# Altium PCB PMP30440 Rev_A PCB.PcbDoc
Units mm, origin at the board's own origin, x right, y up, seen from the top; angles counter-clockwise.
Board outline 51.56 x 18.03 mm, 2 copper layers (Top Layer, Bottom Layer), stack 1.575 mm thick; 21 components, 15 nets, 54 pads, 22 vias.
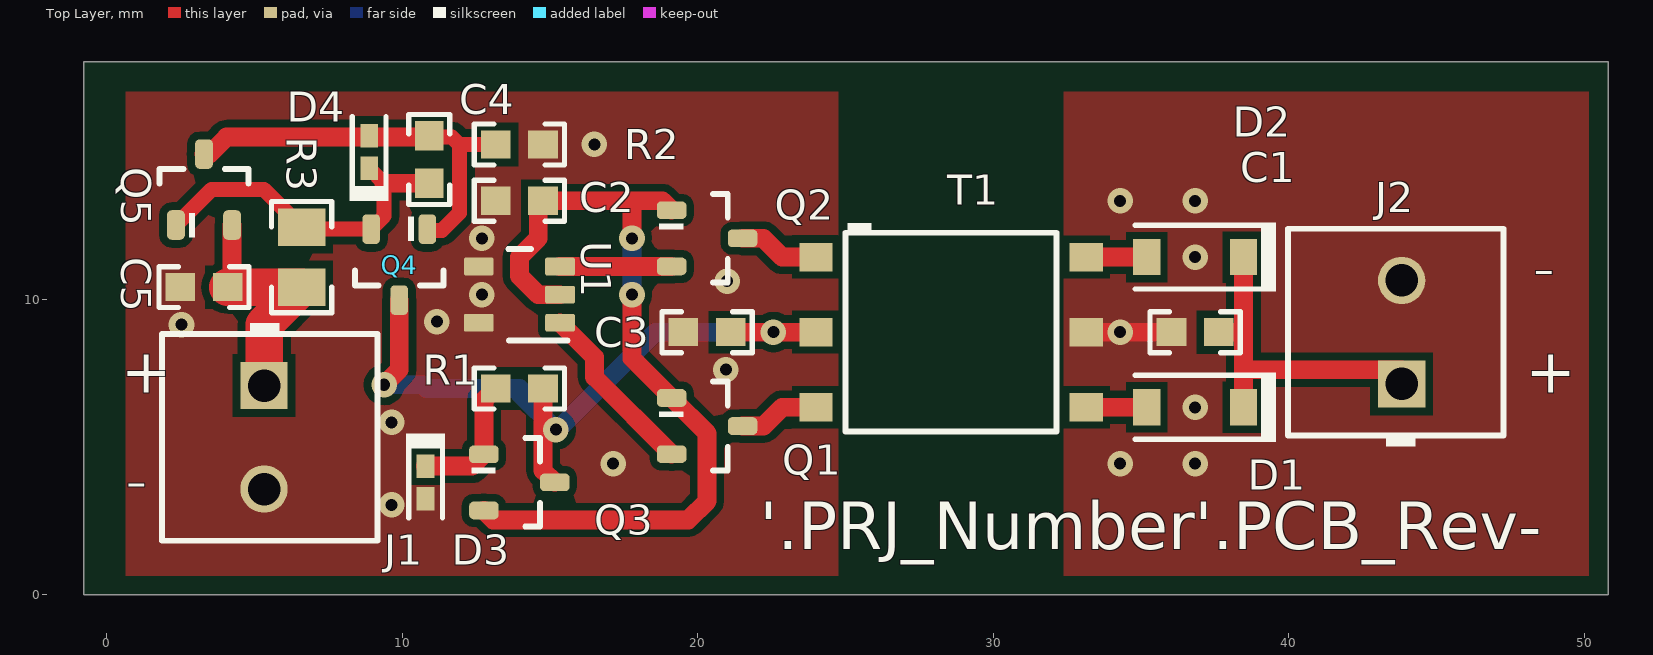
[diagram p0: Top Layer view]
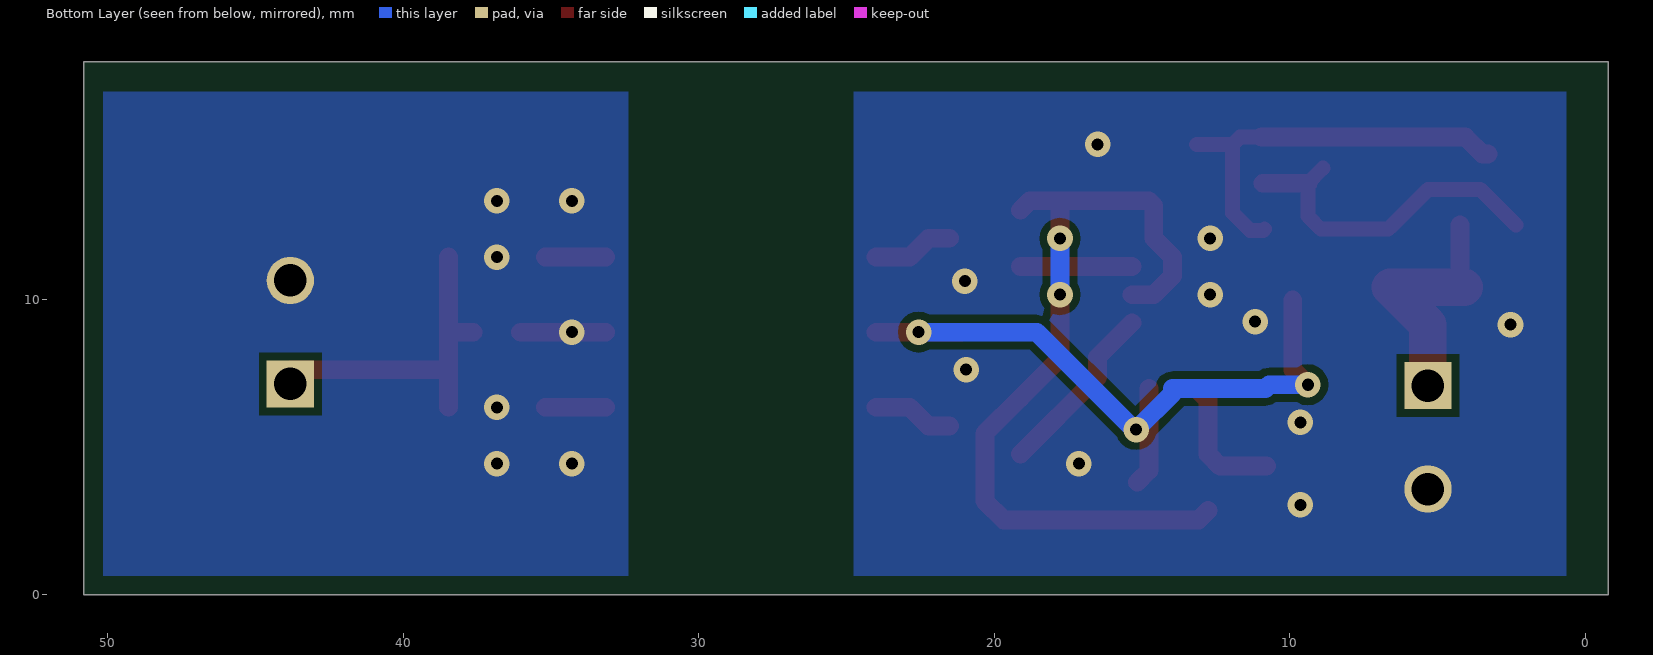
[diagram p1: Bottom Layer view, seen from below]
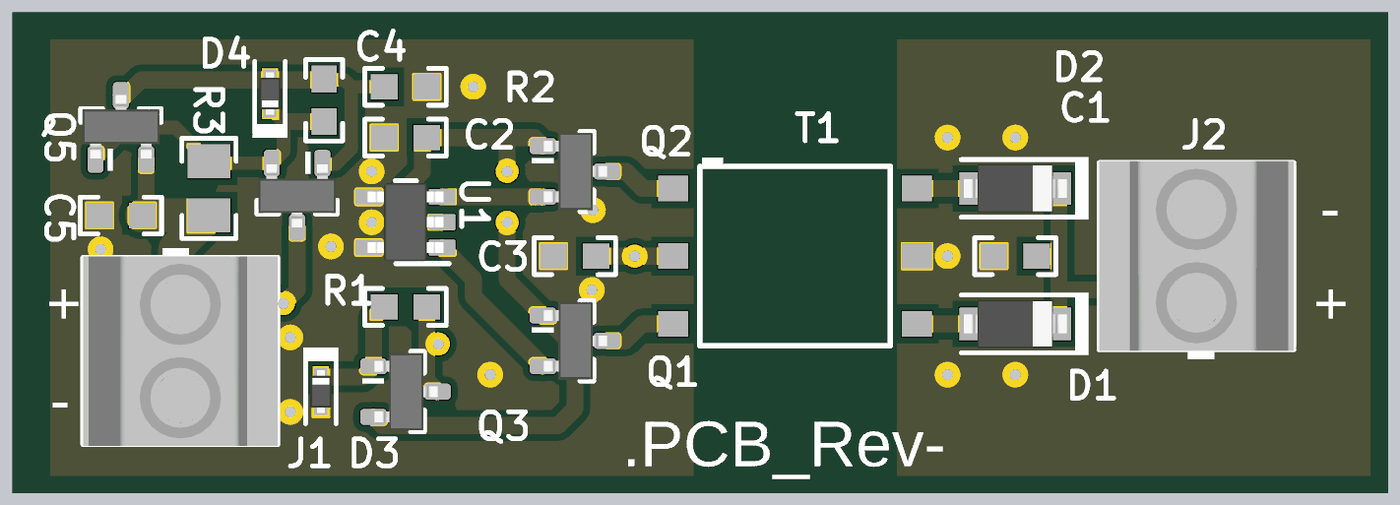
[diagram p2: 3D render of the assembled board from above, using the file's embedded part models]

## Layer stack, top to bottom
Top Solder: solder mask 0.0102, Solder Resist, Dk 3.5
Top Layer: signal copper 0.0356
Dielectric1: core 1.5037, FR-4, Dk 4.8
Bottom Layer: signal copper 0.0356
Bottom Solder: solder mask 0.0102, Solder Resist, Dk 3.5

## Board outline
-0.762,0 50.8,0 50.8,18.034 -0.762,18.034

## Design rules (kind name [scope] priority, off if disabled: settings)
AcuteAngle [All] p1: minimum=4.50000000000000E+0001 checktracksonly=FALSE
AssemblyTestPointUsage [All] p1: valid=2
BoardOutlineClearance BoardOutlineClearance_MountingHoles [OnCopper and InComponentClass('Mounting Holes')] p1: gap=1.016 ignorepadtopadclearanceinfootprint=FALSE
BoardOutlineClearance BoardOutlineClearance_Poly [OnCopper and IsPoly] p2: gap=0.635 ignorepadtopadclearanceinfootprint=FALSE
BoardOutlineClearance [OnCopper and Not InComponentClass('Logo') and not InComponentClass('FiducialMark') and not InRegion(1000,500,4000,800) and not InPoly] p3: gap=1.905 ignorepadtopadclearanceinfootprint=FALSE
Clearance Clearance_4 [InNamedPolygon('TOP_LAYER_GND-S_P006')] p1: gap=0.254 ignorepadtopadclearanceinfootprint=FALSE except(0: Arc-Hole Track-Hole SMDPad-Hole THPad-Hole Via-Hole Fill-Hole Poly-Hole Region-Hole Text-Hole)
Clearance Clearance_3 [InNamedPolygon('BOTTOM_LAYER_GND-S_P004')] p2: gap=0.254 ignorepadtopadclearanceinfootprint=FALSE except(0: Arc-Hole Track-Hole SMDPad-Hole THPad-Hole Via-Hole Fill-Hole Poly-Hole Region-Hole Text-Hole)
Clearance Clearance_2 [InNamedPolygon('BOTTOM_LAYER_GND-P_P002')] p3: gap=0.254 ignorepadtopadclearanceinfootprint=FALSE except(0: Arc-Hole Track-Hole SMDPad-Hole THPad-Hole Via-Hole Fill-Hole Poly-Hole Region-Hole Text-Hole)
Clearance Clearance_1 [InNamedPolygon('TOP_LAYER_GND-P_P000')] p4: gap=0.254 ignorepadtopadclearanceinfootprint=FALSE except(0: Arc-Hole Track-Hole SMDPad-Hole THPad-Hole Via-Hole Fill-Hole Poly-Hole Region-Hole Text-Hole)
Clearance Clearance_Keepouts [((IsTrack Or IsArc) And Not InPoly) And IsFree and IsKeepOut vs ((IsTrack Or IsArc) And Not InPoly) And IsFree and IsKeepOut] p5: gap=0 ignorepadtopadclearanceinfootprint=FALSE
Clearance Clearance_Poly [InPolygon] p6: gap=0.635 ignorepadtopadclearanceinfootprint=FALSE except(0: Arc-Hole Track-Hole SMDPad-Hole THPad-Hole Via-Hole Fill-Hole Poly-Hole Region-Hole Text-Hole)
Clearance Clearance_FiducialMark [IsKeepOut and InComponentClass('FiducialMark') vs IsPad and InComponentClass('FiducialMark')] p7: gap=0 ignorepadtopadclearanceinfootprint=FALSE
Clearance [All] p8: gap=0.2 ignorepadtopadclearanceinfootprint=FALSE except(0: Arc-Hole Track-Hole SMDPad-Hole THPad-Hole Via-Hole Fill-Hole Poly-Hole Region-Hole Text-Hole)
ComponentClearance ComponentClearance_MountingHoles_FiducialMarks [InComponentClass('Mounting Holes') vs InComponentClass('FiducialMark')] p1: gap=1.27 collisioncheckmode=3 verticalgap=0.254 showdistances=FALSE
ComponentClearance ComponentClearance_Shunt [InComponentClass('Header') vs InComponentClass('Shunt')] p2: gap=0 collisioncheckmode=3 verticalgap=0 showdistances=FALSE
ComponentClearance ComponentClearance_Logo [InComponentClass('Logo')] p3: gap=1.27 collisioncheckmode=3 verticalgap=0.254 showdistances=FALSE
ComponentClearance ComponentClearance_ScrewToNut [(HasFootprint('NY PMS 440 0025 PH')) vs (HasFootprint('Keystone_1902C'))] p4: gap=0.127 collisioncheckmode=3 verticalgap=0.254 showdistances=FALSE
ComponentClearance ComponentClearance_MountingHoles [InComponentClass('Mounting Holes')] p5: gap=6.35 collisioncheckmode=3 verticalgap=2540 showdistances=FALSE
ComponentClearance ComponentClearance_SmallPassives [HasFootprint('0201*') or HasFootprint('0402*') or HasFootprint('0508') or HasFootprint('0603*') or HasFootprint('0612') or HasFootprint('0805*') or HasFootprint('0815*') or HasFootprint('0830*') or HasFootprint('1206*') or HasFootprint('1210*') or HasFootprint('1808*') or HasFootprint('1812*') or HasFootprint('1825*') or HasFootprint('2010*') or HasFootprint('2220*') or HasFootprint('2225*') or HasFootprint('2512*') or HasFootprint('2728*') or HasFootprint('3518*') vs HasFootprint('0201*') or HasFootprint('0402*') or HasFootprint('0508') or HasFootprint('0603*') or HasFootprint('0612') or HasFootprint('0805*') or HasFootprint('0815*') or HasFootprint('0830*') or HasFootprint('1206*') or HasFootprint('1210*') or HasFootprint('1808*') or HasFootprint('1812*') or HasFootprint('1825*') or HasFootprint('2010*') or HasFootprint('2220*') or HasFootprint('2225*') or HasFootprint('2512*') or HasFootprint('2728*') or HasFootprint('3518*')] p6: gap=0.38 collisioncheckmode=3 verticalgap=0.254 showdistances=FALSE
ComponentClearance ComponentClearance_THtoSMT [IsThruComponent vs IsSMTComponent] p7: gap=1.016 collisioncheckmode=3 verticalgap=0.762 showdistances=FALSE
ComponentClearance ComponentClearance_THtoTH [IsThruComponent vs IsThruComponent] p8: gap=0.762 collisioncheckmode=3 verticalgap=0.762 showdistances=FALSE
ComponentClearance [All] p9: gap=0.762 collisioncheckmode=3 verticalgap=0.254 showdistances=FALSE
DiffPairsRouting [All] p1: maxlimit=2.54 minlimit=0.254 mostfreqgap=0.254 toplayer_minwidth=0.381 toplayer_maxwidth=0.381 toplayer_prefwidth=0.381 bottomlayer_minwidth=0.381 bottomlayer_maxwidth=0.381 bottomlayer_prefwidth=0.381 maxuncoupledlength=25.4
FabricationTestPointUsage TestPointUsage [All] p1: valid=2 allowmultiple=FALSE
FabricationTestpoint Testpoint [All] p1: side=3 testpointundercomponent=TRUE minsize=1.016 maxsize=2.54 preferedsize=1.524 minholesize=0 maxholesize=1.016 preferedholesize=0.813 testpointgrid=0.025 allowsidetop=TRUE allowsidebottom=TRUE usegrid=TRUE gridtolerance=0
FanoutControl Fanout_LCC [IsLCC] p1: bgadir=Out bgaviamode=Centered fanoutstyle=Auto fanoutdirection=Alternating viagrid=0.025 // Fanout_LCC (Default Rule)
FanoutControl Fanout_BGA [IsBGA] p2: bgadir=Out bgaviamode=Centered fanoutstyle=Auto fanoutdirection=Alternating viagrid=0.025 // Fanout_BGA (Default Rule)
FanoutControl Fanout_Default [All] p4: bgadir=Out bgaviamode=Centered fanoutstyle=Auto fanoutdirection=Alternating viagrid=0.025 // Fanout_Default (Default Rule)
FanoutControl Fanout_Small [(CompPinCount < 5)] p5: bgadir=Out bgaviamode=Centered fanoutstyle=Auto fanoutdirection=OutThenIn viagrid=0.025 // Fanout_Small (Default Rule)
HoleSize [All] p1: absolutevalues=TRUE maxlimit=6.375 minlimit=0.3 maxpercent=80.000 minpercent=20.000
MinimumAnnularRing MinimumAnnularRing_ThermalPadVias [IsVia and InAnyComponent] p1: minimumring=0.15
MinimumAnnularRing [All] p2: minimumring=0.203
MinimumSolderMaskSliver MinimumSolderMaskSliver_Logo [InComponentClass('Logo') vs InComponentClass('Logo')] p1: minsoldermaskwidth=0.018
MinimumSolderMaskSliver [All] p2: minsoldermaskwidth=0.1
PlaneConnect [All] p1: planeconnectstyle=Relief reliefexpansion=0.254 reliefentries=4 reliefconductorwidth=0.254 reliefairgap=0.254
PolygonConnect [All] p1: connectstyle=Direct reliefconductorwidth=0.254 reliefentries=4 polygonreliefangle="90 Angle" airgapwidth=0.254
RoutingVias ThermalPadVias [IsVia and InAnyComponent] p1: holewidth=0.3 width=0.5 viastyle="Through Hole" minholewidth=0.3 minwidth=0.6 maxholewidth=0.33 maxwidth=0.6
RoutingVias [All] p2: holewidth=0.406 width=0.864 viastyle="Through Hole" minholewidth=0.3 minwidth=0.66 maxholewidth=1.016 maxwidth=1.651
SilkToBoardRegionClearance [Not ((IsComment or IsDesignator) And (Hide <> 'False')) and not InRegion(1000,500,4000,800)] p1:
SilkToSilkClearance SilkToSilkClearance_Pb-FreeLogo [(HasFootprint('Pb-Free_Overlay_Medium') OR HasFootprint('Pb-Free_Overlay_Small')) vs (HasFootprint('Pb-Free_Overlay_Medium') OR HasFootprint('Pb-Free_Overlay_Small'))] p1: silktosilkclearance=0
SilkToSilkClearance [All] p2: silktosilkclearance=0.102
SilkToSolderMaskClearance SilkToComponentPadClearance [(IsPad or IsFill or IsRegion) and InAnycomponent] p1: minsilkscreentomaskgap=0.127 clearancetoexposedcopper=TRUE
SilkToSolderMaskClearance "Silk to Solder Mask Opening" [All] p2: minsilkscreentomaskgap=0.102 clearancetoexposedcopper=FALSE
SolderMaskExpansion [All] p1: expansion=0.05
Width [All] p1: maxlimit=2.54 minlimit=0.152 preferedwidth=0.254 checkconnectedcopper=TRUE
15 further rules are at their usual default settings.

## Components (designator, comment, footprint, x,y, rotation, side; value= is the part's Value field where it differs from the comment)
C1 "C1608X5R1H105K080AB" 0603 36.83,8.89 r180 top value=1uF
C2 "C1608X5R1H105K080AB" 0603 13.97,13.335 r180 top value=1uF
C3 "C1608X5R1H105K080AB" 0603 20.32,8.89 r180 top value=1uF
C4 "GRM188R61H102KA01D" 0603 10.922,14.732 r90 top value=1000pF
C5 "C1608X5R1H105K080AB" 0603 3.302,10.414 r180 top value=1uF
D1 "MBR0540T1G" SOD-123 36.83,6.35 r180 top value=40V
D2 "MBR0540T1G" SOD-123 36.83,11.43 r180 top value=40V
D3 "BZT52C5V6T-7" SOD-523 10.795,3.81 r270 top value=5.6V
D4 "BZT52C12T-7" SOD-523 8.89,14.986 r90 top value=12V
J1 "39357-0002" Molex_39357-0002 5.334,5.334 r270 top
J2 "39357-0002" Molex_39357-0002 43.815,8.89 r90 top
Q1 "BSS123" SOT-23 20.32,5.715 r0 top value=100V
Q2 "BSS123" SOT-23 20.32,12.065 r0 top value=100V
Q3 "MMBT3904LT1G" SOT-23 13.97,3.81 r0 top value="40 V"
Q4 "NTR5105P" SOT-23 9.906,11.176 r270 top
Q5 "MMBT3906" SOT-23 3.302,13.716 r90 top value="40 V"
R1 "RC0603FR-07150KL" 0603 13.97,6.985 r0 top value=150k
R2 "CRCW0603100KFKEA" 0603 13.97,15.24 r180 top value=100k
R3 "CRCW08054R02FKEA" 0805_HV 6.604,11.43 r90 top value=4.02
T1 "750317331" Wurth_760390012 28.575,8.89 r0 top
U1 "SN6501DBVR" DBV0005A_N 13.97,10.16 r180 top

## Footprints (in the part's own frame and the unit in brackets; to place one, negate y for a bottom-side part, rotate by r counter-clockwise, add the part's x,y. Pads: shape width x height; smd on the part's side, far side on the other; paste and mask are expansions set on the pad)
0603 [mm] "0603 from SM-752 data"
  rect 1x0.95 smd: 1(-0.8,0) 2(0.8,0)
  silkscreen extent -1.52,-0.69 1.52,0.69, body extent -0.87,-0.47 0.87,0.47, height 1
0805_HV [mil] "0805 with 30mil clearance between pads"
  rect 50x63 smd: 1(-40,0) 2(40,0)
  silkscreen extent -74,-40 74,40, body extent -43,-29 43,29, height 57
DBV0005A_N [mm] "SOT23, 5-Leads, Body 2.9x1.6mm, Pitch 0.95mm, Lead Span 2.8mm, IPC Medium Density"
  rrect17% 1x0.6 smd: 1(-1.375,0.95) 2(-1.375,0) 3(-1.375,-0.95) 4(1.375,-0.95) 5(1.375,0.95)
  silkscreen extent -1.63,-1.55 0.38,1.55, body extent -1.42,-1.46 1.42,1.46, height 1.09
Molex_39357-0002 [mm] "Terminal Block, 3.5 mm, 2x1, TH"
  rect 1.6x1.6 hole 1.1: 1(-1.75,0)
  round 1.6 hole 1.1: 2(1.75,0)
  silkscreen extent -3.86,-3.45 3.5,3.84, body extent -3.55,-3.45 3.56,3.84, height 8.51
SOD-123 [mm] "On Semi recommended land pattern"
  rect 0.915x1.22 smd: 1(-1.637,0) 2(1.637,0)
  silkscreen extent -2.74,-1.17 2.03,1.17, body extent -1.93,-0.9 1.93,0.9, height 1.35
SOD-523 [mm] "NXP Semiconductor recommended land pattern, nominal STEP model"
  rect 0.8x0.6 smd paste-0.05: 1(-0.55,0) 2(0.55,0)
  silkscreen extent -1.65,-0.66 1.2,0.66, body extent -0.8,-0.4 0.8,0.4, height 0.72
SOT-23 [mm] "SOT23, 3-Leads, Body 2.9x1.3mm, Pitch 0.95mm, Lead Span 2.5mm, IPC Medium Density"
  rrect50% 1x0.6 smd: 1(-1.2,0.95) 2(-1.2,-0.95) 3(1.2,0)
  silkscreen extent -1.63,-1.5 0.7,1.5, body extent -1.16,-1.45 1.21,1.45, height 1
Wurth_760390012 [mm] "SMD, 6-Leads, Body 7.14x6.73mm, Pitch 2.54mm"
  rect 1.12x0.96 smd: 1(-4.57,2.54) 2(-4.57,0) 3(-4.57,-2.54) 4(4.57,-2.54) 5(4.57,0) 6(4.57,2.54)
  silkscreen extent -3.57,-3.36 3.57,3.7, body extent -5.02,-3.36 5.02,3.36, height 4.2

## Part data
C1 C2 C3 C5: "CAP, CERM, 1 µF, 50 V,+/- 10%, X5R, 0603", Cap_Case=0603, Manufacturer=TDK, Supplier Part Number 1=445-7468-1-ND, TempCo=X5R, Tolerance_%=10, Value1="0.005522 ohm", Value2=50V, ValueDisplayed=1µF
C4: "CAP, CERM, 1000 pF, 50 V,+/- 10%, X5R, 0603", Cap_Case=0603, Manufacturer=MuRata, Supplier Part Number 1=GRM188R61H102KA01D-ND, TempCo=X5R, Tolerance_%=10, Value2=50V, ValueDisplayed=1000pF
D1 D2: "Diode, Schottky, 40 V, 0.5 A, SOD-123", Manufacturer="ON Semiconductor", Supplier Part Number 1=MBR0540T1GOSCT-ND, Value1=0.5A, Value2=0.51V
D3: "Diode, Zener, 5.6 V, 300 mW, SOD-523", Manufacturer="Diodes Inc.", Power_W=0.3, Supplier Part Number 1=BZT52C5V6TDICT-ND, Value1=0.3W
D4: "Diode, Zener, 12 V, 300 mW, SOD-523", Manufacturer="Diodes Inc.", Power_W=0.3, Supplier Part Number 1=BZT52C12T-7DICT-ND, Value1=0.3W
J1 J2: "Terminal Block, 3.5 mm, 2x1, Tin, TH", Manufacturer=Molex, Supplier Part Number 1=WM7877-ND
Q1 Q2: "MOSFET, N-CH, 100 V, 0.17 A, SOT-23", Alternate Manufacturer=None, Manufacturer="Fairchild Semiconductor", Supplier Part Number 1=BSS123NCT-ND, Value1="10 ohm", Value2="1.8 nC"
Q3: library part "MMBT3904LT1G, ON Semiconductor", "Transistor, NPN, 40 V, 0.2 A, SOT-23", Manufacturer="ON Semiconductor", Supplier Part Number 1=MMBT3904LT1GOSCT-ND, Value1="0.2 A", Value2=300
Q4: library part BSR316PH6327XTSA1, "MOSFET, P-CH, -60 V, -0.211 A, SOT-23", Alternate Manufacturer=None, Manufacturer="ON Semiconductor", Value1="5 ohm", Value2="1 nC"
Q5: library part "MMBT3906, Fairchild Semiconductor", "Transistor, PNP, 40 V, 0.2 A, SOT-23", Manufacturer="Fairchild Semiconductor", Supplier Part Number 1=MMBT3906FSCT-ND, Value1="0.2 A", Value2=300
R1: "RES, 150 k, 1%, 0.1 W, 0603", Manufacturer="Yageo America", Power_W=0.1, Supplier Part Number 1=311-150KHRCT-ND, TempCo="200 ppm/C", Tolerance_%=1, Value1=1%, Value2=0.1W, Value_Code=150k
R2: "RES, 100 k, 1%, 0.1 W, 0603", Manufacturer=Vishay-Dale, Power_W=0.1, Supplier Part Number 1=541-100KHCT-ND, TempCo="100 ppm/C", Tolerance_%=1, Value1=1%, Value2=0.1W, Value_Code=100k
R3: "RES, 4.02, 1%, 0.125 W, 0805", Manufacturer=Vishay-Dale, Power_W=0.125, Supplier Part Number 1=541-4.02CCCT-ND, TempCo="100 ppm/C", Tolerance_%=1, Value1=1%, Value2=0.125W, Value_Code=4R02, ValueDisplayed=4.02
T1: library part 760390012, "Transformer, 1 mH, SMT", Manufacturer="Wurth Elektronik", ValueDisplayed=1mH
U1: "Low-Noise 350 mA, 410 kHz Transformer Driver, DBV0005A (SOT-23-5)", Alternate Manufacturer="Texas Instruments", Alternate PartNumber=SN6501DBVT

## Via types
v1: diameter 0.864, hole 0.406, Top Layer to Bottom Layer, 22 vias

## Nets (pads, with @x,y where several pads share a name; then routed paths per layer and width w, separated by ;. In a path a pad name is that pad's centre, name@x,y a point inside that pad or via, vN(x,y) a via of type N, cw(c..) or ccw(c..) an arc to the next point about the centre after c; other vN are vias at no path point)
GND-P: C2.2 C3.2 C5.2 D3.2 J1.2 R2.1 U1.4 U1.5
  other v1: 9.652,3.048 17.145,4.445 9.652,5.842 20.955,7.62 2.54,9.144 11.176,9.251 12.7,10.16 20.995,10.615 12.7,12.065 16.51,15.24
GND-S: C1.2 J2.2 T1.5 | length 2.9
  Top Layer w0.635: T1.5 C1.2
  other v1: 34.29,4.445 36.83,4.445 36.83,6.35 34.29,8.89 36.83,11.43 34.29,13.335 36.83,13.335
NetC1_1: C1.1 D1.1 D2.1 J2.1 | length 11.3
  Top Layer w0.635: C1.1 38.467,8.89 ; D1.1 38.467,7.62 ; D2.1 38.467,8.89 ; J2.1@43.815,7.62 38.467,7.62 ; 38.467,7.62 38.467,8.89
NetC2_1: C2.1 Q1.1 Q2.1 Q3.2 U1.2 | length 28.1
  Top Layer w0.635: Q3.2 13.09,2.54 19.685,2.54 20.32,3.175 20.32,5.465 Q1.1 17.78,8.005 v1(17.78,10.16) ; U1.2 14.605,10.16 13.97,10.795 13.97,11.43 14.605,12.065 14.605,13.17 C2.1 17.78,13.335 ; v1(17.78,12.065) 17.78,13.335 ; Q2.1 18.8,13.335 17.78,13.335
  Bottom Layer w0.635: v1(17.78,10.16) v1(17.78,12.065)
NetC3_1: C3.1 Q3.3 Q4.3 R1.2 T1.2 | length 25
  Top Layer w0.635: v1(9.398,7.112) 9.906,7.62 Q4.3 ; R1.2 14.77,5.598 ; Q3.3 14.77,4.21 14.77,5.598 ; v1(15.202,5.598) 14.77,5.598 ; C3.1 v1(22.562,8.89) T1.2
  Bottom Layer w0.635: v1(9.398,7.112) 10.698,7.112 10.825,6.985 13.97,6.985 13.97,6.83 v1(15.202,5.598) 15.24,5.56 18.57,8.89 v1(22.562,8.89)
NetC4_1: C4.1 D4.1 Q4.2 Q5.1 R3.2 | length 11.6
  Top Layer w0.508: Q5.1 3.552,13.716 5.334,13.716 R3.2 6.674,12.376 Q4.2 9.394,12.814 9.394,13.932 D4.1
  Top Layer w0.635: 9.394,13.932 C4.1
NetC4_2: C4.2 D4.2 Q4.1 Q5.3 R2.2 | length 13.9
  Top Layer w0.508: Q4.1 10.896,12.336 11.356,12.336 11.938,12.918 11.938,15.24 ; C4.2 10.96,15.494 11.684,15.494 11.938,15.24 ; R2.2 11.938,15.24
  Top Layer w0.635: Q5.3 3.486,14.916 4.064,15.494 C4.2@10.96,15.494
NetC5_1: C5.1 J1.1 Q5.2 R3.1 | length 8.5
  Top Layer w0.635: C5.1 4.252,10.564 Q5.2
  Top Layer w1.27: C5.1 R3.1 5.334,9.144 J1.1
NetD1_2: D1.2 T1.4 | length 2
  Top Layer w0.635: T1.4 D1.2
NetD2_2: D2.2 T1.6 | length 2
  Top Layer w0.635: T1.6 D2.2
NetD3_1: D3.1 Q3.1 R1.1 | length 4.5
  Top Layer w0.635: D3.1 12.37,4.36 Q3.1 12.77,6.585 R1.1
NetQ1_2: Q1.2 U1.1 | length 6
  Top Layer w0.635: U1.1 16.51,8.045 16.51,7.375 Q1.2
NetQ1_3: Q1.3 T1.3 | length 2.7
  Top Layer w0.635: Q1.3 22.225,5.715 22.86,6.35 T1.3
NetQ2_2: Q2.2 U1.3 | length 3.8
  Top Layer w0.635: U1.3 19.115,11.11 Q2.2
NetQ2_3: Q2.3 T1.1 | length 2.7
  Top Layer w0.635: Q2.3 22.225,12.065 22.86,11.43 T1.1

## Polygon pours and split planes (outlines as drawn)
GND-P on Top Layer "TOP_LAYER_GND-P_P000" (solid, remove dead copper, pour order 0): 0.635,17.018 24.765,17.018 24.765,0.635 0.635,0.635
GND-S on Top Layer "TOP_LAYER_GND-S_P006" (solid, remove dead copper, pour order 6): 32.385,17.018 50.165,17.018 50.165,0.635 32.385,0.635
GND-P on Bottom Layer "BOTTOM_LAYER_GND-P_P002" (solid, remove dead copper, pour order 2): 0.635,17.018 24.765,17.018 24.765,0.635 0.635,0.635
GND-S on Bottom Layer "BOTTOM_LAYER_GND-S_P004" (solid, remove dead copper, pour order 4): 32.385,17.018 50.165,17.018 50.165,0.635 32.385,0.635

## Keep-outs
Keep-Out Layer:
  text ".Layer_Name" at 14.656,-21.806 h1.52

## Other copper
Top Layer:
  text ".Layer_Name" at 55.372,28.448 h1.52
Bottom Layer:
  text ".Layer_Name" at 14.656,-21.806 h1.52

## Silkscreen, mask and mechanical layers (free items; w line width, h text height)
Top Overlay:
  text "-" at 48.26,9.906 h2.54
  text "+" at 0.508,6.35 h2.54
  text "+" at 48.006,6.35 h2.54
  text "-" at 0.647,2.71 h2.54
  text "'.PRJ_Number'.PCB_Rev-" at 22.098,1.016 h2.75
  text ".Layer_Name" at 14.656,-21.806 h1.52
Bottom Overlay:
  text ".Layer_Name" at 14.656,-21.806 h1.52
Top Paste:
  text ".Layer_Name" at 14.656,-21.806 h1.52
Bottom Paste:
  text ".Layer_Name" at 14.656,-21.806 h1.52
Top Solder:
  text ".Layer_Name" at 14.656,-21.806 h1.52
  text ".Layer_Name" at 14.656,-21.806 h1.52
Bottom Solder:
  text ".Layer_Name" at 14.656,-21.806 h1.52
Drill Guide:
  text ".Layer_Name" at 14.656,-21.806 h1.52
M1 Board Outline:
  the board outline again, w0.254
  text ".Layer_Name" at 55.626,24.892 h1.52
M2 Board Dimensions:
  rectangle: 3.175,-10.16 12.7,-6.985
  rectangle: 0,-6.985 3.175,-3.81
  lines w0.178: 0,-6.985 25.4,-6.985 ; 3.175,-10.16 3.175,-3.81 ; 6.35,-10.16 6.35,-3.81 ; 12.7,-10.16 12.7,-3.81 ; 19.05,-10.16 19.05,-3.81 ; 0,-10.16 0,-3.81 25.4,-3.81 25.4,-10.16 0,-10.16
  text ".Layer_Name" at 55.626,22.098 h1.52
M3 3D STEP Top:
  text ".Layer_Name" at 14.656,-21.806 h1.52
M4 3D STEP Bottom:
  text ".Layer_Name" at 14.656,-21.806 h1.52
M5 Assembly Top:
  lines w0.254: -7.417,-23.626 160.223,-23.626 ; -7.417,-18.462 160.274,-18.462 ; -7.417,-13.297 -7.417,-28.791 94.31,-28.791 160.274,-28.791 160.274,-13.297 -7.404,-13.297 -7.404,-28.791 32.614,-28.791 ; 55.194,-28.791 55.194,-13.297 ; 87.376,-18.462 87.376,-13.297 ; 108.712,-18.462 108.712,-13.297 ; 124.511,-28.956 124.511,-23.804
  text "COMPONENTS MARKED 'DNP' SHOULD NOT BE POPULATED." at 29.299,-8.09 h1.52
  text "ASSEMBLY VARIANT:" at 29.286,-11.024 h1.52
  text ".VariantName" at 55.601,-11.024 h1.52
  text "PCB VIEWED FROM TOP SIDE" at -5.804,-16.654 h1.52
  text "BOARD #:" at 57.099,-16.654 h1.52
  text ".PRJ_Number" at 70.955,-16.654 h1.52
  text "REV:" at 92.405,-16.654 h1.52
  text ".PCB_Rev" at 99.809,-16.654 h1.52
  text "SVN REV:" at 113.69,-16.654 h1.52
  text ".VersionControl_RevNumber" at 126.543,-16.654 h1.52
  text "TID #:" at 57.099,-21.819 h1.52
  text ".TID" at 70.955,-21.819 h1.52
  text "PLOT NAME =" at -5.804,-27.034 h1.52
  text ".plot_File_Name" at 14.656,-27.034 h1.52
  text "GENERATED    :" at 57.15,-27.034 h1.52
  text ".Print_Date" at 79.235,-27.034 h1.52
  text ".Print_Time" at 97.752,-27.034 h1.52
  text "TEXAS INSTRUMENTS" at 129.87,-27.034 h1.52
M6 Assembly Bottom:
  lines w0.254: -7.429,-18.474 160.261,-18.474 ; -7.379,-23.639 160.261,-23.639 ; 28.334,-28.969 28.334,-23.817 ; 44.133,-18.474 44.133,-13.31 ; 65.468,-18.474 65.468,-13.31 ; 97.65,-28.804 97.65,-13.31 ; 120.231,-28.804 160.249,-28.804 160.249,-13.31 -7.429,-13.31 -7.429,-28.804 58.534,-28.804 160.261,-28.804 160.261,-13.31
  text "COMPONENTS MARKED 'DNP' SHOULD NOT BE POPULATED." at 154.991,-8.077 h1.52
  text ".VariantName" at 128.473,-11.024 h1.52
  text "ASSEMBLY VARIANT:" at 154.864,-11.024 h1.52
  text ".VersionControl_RevNumber" at 26.302,-16.667 h1.52
  text "SVN REV:" at 39.154,-16.667 h1.52
  text ".PCB_Rev" at 53.035,-16.667 h1.52
  text "REV:" at 60.439,-16.667 h1.52
  text ".PRJ_Number" at 81.89,-16.667 h1.52
  text "BOARD #:" at 95.745,-16.667 h1.52
  text "PCB VIEWED FROM BOTTOM SIDE" at 158.648,-16.667 h1.52
  text ".TID" at 81.89,-21.831 h1.52
  text "TID #:" at 95.745,-21.831 h1.52
  text "TEXAS INSTRUMENTS" at 22.974,-27.047 h1.52
  text ".Print_Time" at 55.093,-27.047 h1.52
  text ".Print_Date" at 73.609,-27.047 h1.52
  text "GENERATED    :" at 95.694,-27.047 h1.52
  text ".plot_File_Name" at 138.189,-27.047 h1.52
  text "PLOT NAME =" at 158.648,-27.047 h1.52
M9 Title Sheet:
  drawing of 57 lines, arcs and shapes, not listed
  text "1" at 18.792,204.127 h1.78
  text "2" at 82.182,204.127 h1.78
  text "3" at 145.411,204.127 h1.78
  text "4" at 209.08,204.127 h1.78
  text "5" at 272.555,204.127 h1.78
  text "6" at 336.182,204.127 h1.78
  text "A" at -10.579,175.095 h1.78
  text "A" at 365.341,175.095 h1.78
  text "B" at -10.579,114.643 h1.78
  text "B" at 365.341,114.643 h1.78
  text "C" at -10.579,54.318 h1.78
  text "C" at 365.341,54.318 h1.78
  text ".Layer_Name" at 55.372,18.796 h1.52
  text "PROJECT TITLE:" at 288.125,7.048 h1.14
  text ".PRJ_Title" at 289.395,3.662 h1.78
  text "DESIGNED FOR:" at 288.125,-0.597 h1.14
  text ".PRJ_Customer" at 289.395,-4.153 h1.78
  text "D" at -10.579,-5.88 h1.78
  text "D" at 365.341,-5.88 h1.78
  text "FILE NAME:" at 288.125,-8.217 h1.14
  text ".PCB_File_Name_No_Path" at 289.395,-11.265 h1.78
  text "Texas Instruments (TI) and/or its licensors do not warrant the accuracy or completeness of this specification" at 161.9,-15.376 h1.14
  text "ENGINEER:" at 288.125,-15.583 h1.14
  text "LAYOUT BY:" at 326.352,-15.583 h1.14
  text "or any information contained therein. TI and/or its licensors do not warrant that this design will meet" at 160.757,-18.237 h1.14
  text ".PRJ_Engineer" at 289.395,-19.52 h1.78
  text ".PCB_Layout" at 327.635,-19.52 h1.78
  text "the specifications, will be suitable for your application or fit for any particular purpose, or will operate in" at 160.757,-21.099 h1.14
  text "ALTIUM DESIGNER VERSION:" at 326.352,-23.457 h1.14
  text "an implementation. TI and/or its licensors do not warrant that the design is production worthy. You should" at 160.757,-23.961 h1.14
  text "completely validate and test your design implementation to confirm the system functionality for your application." at 161.9,-26.822 h1.14
  text ".print_Scale" at 289.395,-26.843 h1.78
  text ".Application_BuildNumber" at 327.635,-26.843 h1.78
  text "1" at 18.792,-32.093 h1.78
  text "2" at 82.182,-32.093 h1.78
  text "3" at 145.411,-32.093 h1.78
  text "4" at 209.08,-32.093 h1.78
  text "5" at 272.555,-32.093 h1.78
  text "6" at 336.182,-32.093 h1.78
M10 Fab Notes:
  drawing of 189 lines, arcs and shapes, not listed
  text "DESIGN INFORMATION" at 314.503,161.447 h1.52
  text "MIN. TRACK WIDTH:" at 298.131,158.091 h1.52
  text "8" at 325.976,158.091 h1.52
  text "MIL" at 329.907,158.091 h1.52
  text "MIN. CLEARANCE:" at 298.131,154.938 h1.52
  text "0.2" at 324.452,154.938 h1.52
  text "mm" at 329.907,154.938 h1.52
  text "MIN. VIA PAD SIZE:" at 298.131,151.785 h1.52
  text "24" at 325.214,151.785 h1.52
  text "MIL" at 329.907,151.785 h1.52
  text "0.05mm (2MIL)" at 315.784,148.486 h1.52
  text "MINIMUM ANNULAR RING" at 289.769,148.277 h1.52
  text "EXTERNAL" at 333.768,148.277 h1.52
  text "PER" at 294.849,145.48 h1.52
  text "IPC-D-275 CLASS 2 LEVEL C" at 300.437,145.48 h1.52
  text "MIL, HOLES" at 338.238,142.928 h1.52
  text "+/-" at 328.27,142.709 h1.52
  text "+/-" at 349.961,142.709 h1.52
  text "REGISTRATION TOLERANCES:" at 289.769,142.682 h1.52
  text "METAL" at 320.243,142.682 h1.52
  text "5" at 334.879,142.683 h1.52
  text "3" at 356.037,142.683 h1.52
  text "MIL" at 358.99,142.682 h1.52
  text "HOLE SIZE TOLERANCE (UNLESS OTHERWISE SPECIFIED):" at 289.769,140.185 h1.52
  text "+/-" at 349.961,140.112 h1.52
  text "3" at 356.037,140.085 h1.52
  text "MIL" at 358.99,140.085 h1.52
  text "MATERIAL:" at 287.87,136.589 h1.52
  text "FR-4 High Tg" at 312.926,133.324 h1.52
  text "X" at 309.257,133.122 h1.52
  text "FR-408" at 298.563,133.007 h1.52
  text "OTHER" at 336.358,133.007 h1.52
  text "62 MIL (1.6mm) +/-10%" at 306.694,129.374 h1.52
  text "X" at 303.643,129.312 h1.52
  text "THICKNESS:" at 289.769,129.165 h1.52
  text "OTHER" at 339.33,129.165 h1.52
  text "TOLERANCE:" at 289.769,125.652 h1.52
  text "X" at 311.314,125.652 h1.52
  text "ANSI IPC-6012 TYPE 3 CLASS 2" at 315.836,125.652 h1.52
  text "OTHER +/-" at 315.835,121.989 h1.52
  text "BOW & TWIST:" at 289.769,118.302 h1.52
  text "X" at 311.314,118.302 h1.52
  text "ANSI IPC-6012 TYPE 3 CLASS 2" at 315.836,118.302 h1.52
  text "OTHER +/-" at 315.835,114.576 h1.52
  text "DRILLING:" at 287.87,111.258 h1.52
  text "NC_DRILL FILES" at 332.599,108.586 h1.52
  text "REFERENCE:" at 289.769,108.486 h1.52
  text "X" at 306.463,108.484 h1.52
  text "AS SHOWN" at 310.984,108.486 h1.52
  text "X" at 329.348,108.486 h1.52
  text "OTHER" at 340.168,104.873 h1.52
  text "PTH COPPER THICKNESS:" at 289.761,104.783 h1.52
  text "X" at 318.697,104.783 h1.52
  text "20-30 um" at 321.948,104.783 h1.52
  text "BOARD FINISH:" at 287.87,101.034 h1.52
  text "SILKSCREEN:" at 291.812,98.237 h1.52
  text "X" at 316.14,98.237 h1.52
  text "TOP" at 319.112,98.237 h1.52
  text "X" at 329.094,98.237 h1.52
  text "BOTTOM" at 332.091,98.237 h1.52
  text "SILKSCREEN COLOR:" at 291.812,94.295 h1.52
  text "X" at 316.115,94.295 h1.52
  text "WHITE" at 319.112,94.295 h1.52
  text "OTHER" at 332.091,94.295 h1.52
  text "X" at 319.442,90.652 h1.52
  text "GREEN" at 322.439,90.652 h1.52
  text "OTHER" at 338.136,90.652 h1.52
  text "SOLDER RESIST COLOR:" at 291.812,90.477 h1.52
  text "X" at 319.442,86.734 h1.52
  text "MATTE" at 322.439,86.734 h1.52
  text "SEMI-GLOSS" at 338.125,86.717 h1.52
  text "IMMERSION GOLD (ENIG)" at 314.819,82.345 h1.52
  text "ENEPIG" at 348.793,82.162 h1.52
  text "SURFACE FINISH:" at 287.87,82.136 h1.52
  text "X" at 310.298,82.136 h1.52
  text "IMM. TIN/SILVER OR EQUIV" at 296.24,78.649 h1.52
  text "OTHER" at 332.599,78.549 h1.52
  text "ARRAY/PANEL:" at 287.87,74.602 h1.52
  text "CUT AND TRIM PER M1 BOARD OUTLINE" at 314.819,74.393 h1.52
  text "N.C. ROUTE" at 314.819,70.94 h1.52
  text "X" at 332.295,70.94 h1.52
  text "V. SCORE" at 336.816,70.94 h1.52
  text "CERTIFICATION:" at 287.87,67.66 h1.52
  text "MATERIALS AND WORKMANSHIP FOR ALL PCBS" at 306.285,67.66 h1.52
  text "TO MEET OR EXCEED THE REQUIREMENTS OF:" at 306.285,65.271 h1.52
  text "X" at 297.078,62.003 h1.52
  text "ANSI IPC-A-600F CLASS ->" at 300.329,62.003 h1.52
  text "X" at 342.188,62.003 h1.52
  text "2" at 344.982,62.003 h1.52
  text "1" at 336.981,61.965 h1.52
  text "3" at 353.973,61.965 h1.52
  text "X" at 317.702,58.252 h1.52
  text "RoHS" at 320.953,58.252 h1.52
  text "OTHER" at 337.321,58.252 h1.52
  text "PER ORDER" at 347.407,58.252 h1.52
  text "ALL BOARDS MUST MEET OR EXCEED UL94-V0 REQUIREMENTS." at 288.569,54.345 h1.52
  text "PCB MUST BEAR THE UL94V-0 UL REGISTERED MATERIAL ID NUMBER" at 288.569,51.397 h1.52
  text "ADDITIONAL REQUIREMENTS:" at 287.87,47.094 h1.52
  text "MICROSECTION:" at 289.769,44.373 h1.52
  text "YES" at 312.775,44.373 h1.52
  text "REQUIRED" at 334.657,40.707 h1.52
  text "BARE BOARD ELEC. TEST:" at 289.769,40.634 h1.52
  text "NONE" at 322.935,40.634 h1.52
  text "X" at 331.66,40.634 h1.52
  text "PER ORDER" at 349.693,40.634 h1.52
  text "XX MIL VIAS REQUIRE NON-CONDUCTIVE FILL AND PLANARIZE" at 294.04,35.428 h1.5
  text "XX MIL VIAS REQUIRE CONDUCTIVE FILL AND PLANARIZE" at 294.243,32.787 h1.52
  text "OUTER XX MIL TRACES REQUIRE 50 OHM SINGLE-ENDED IMPEDANCE" at 294.218,28.637 h1.47
  text "LAYER 2 & 3 (INNER LAYERS) XX MIL WIDE, XX MIL SPACE / TRACES REQUIRE 100 OHM DIFFERENTIAL IMPEDANCE" at 294.015,22.65 h1.52
  text ".Layer_Name" at 55.372,15.24 h1.52
M11 Gerber Information:
  lines w0.254: -7.417,-23.626 160.223,-23.626 ; -7.417,-18.462 160.274,-18.462 ; -7.417,-13.297 -7.417,-28.791 94.31,-28.791 160.274,-28.791 160.274,-13.297 -7.404,-13.297 -7.404,-28.791 32.614,-28.791 ; 55.194,-28.791 55.194,-13.297 ; 87.376,-18.462 87.376,-13.297 ; 108.712,-18.462 108.712,-13.297 ; 124.511,-28.956 124.511,-23.804
  text "ALL ARTWORK VIEWED FROM TOP SIDE" at -5.804,-16.654 h1.52
  text "BOARD #:" at 57.099,-16.654 h1.52
  text ".PRJ_Number" at 70.955,-16.654 h1.52
  text "REV:" at 92.405,-16.654 h1.52
  text ".PCB_Rev" at 99.809,-16.654 h1.52
  text "SVN REV:" at 113.69,-16.654 h1.52
  text ".VersionControl_RevNumber" at 126.543,-16.654 h1.52
  text "LAYER NAME =" at -5.804,-21.806 h1.52
  text "TID #:" at 57.099,-21.819 h1.52
  text ".TID" at 70.955,-21.819 h1.52
  text "PLOT NAME =" at -5.804,-27.034 h1.52
  text ".plot_File_Name" at 14.656,-27.034 h1.52
  text "GENERATED    :" at 57.15,-27.034 h1.52
  text ".Print_Date" at 79.235,-27.034 h1.52
  text ".Print_Time" at 97.752,-27.034 h1.52
  text "TEXAS INSTRUMENTS" at 129.87,-27.034 h1.52
M12 Stackup:
  drawing of 191 lines, arcs and shapes, not listed
  text "Layer" at 248.865,198.882 h1.52
  text "Name" at 259.277,198.882 h1.52
  text "Material" at 282.892,198.882 h1.52
  text "Thickness" at 304.731,198.882 h1.52
  text "Constant" at 321.236,198.882 h1.52
  text "Board Layer Stack" at 335.711,198.882 h1.52
  text "1" at 248.865,195.834 h1.52
  text "Top Overlay" at 259.277,195.834 h1.52
  text "2" at 248.865,192.786 h1.52
  text "Top Solder" at 259.277,192.786 h1.52
  text "Solder Resist" at 282.892,192.786 h1.52
  text "0.40mil" at 304.731,192.786 h1.52
  text "3.5" at 321.236,192.786 h1.52
  text "3" at 248.865,189.738 h1.52
  text "Top Layer" at 259.277,189.738 h1.52
  text "Copper" at 282.892,189.738 h1.52
  text "1.40mil" at 304.731,189.738 h1.52
  text "4" at 248.865,186.69 h1.52
  text "Dielectric1" at 259.277,186.69 h1.52
  text "FR-4" at 282.892,186.69 h1.52
  text "59.20mil" at 304.731,186.69 h1.52
  text "4.8" at 321.236,186.69 h1.52
  text "5" at 248.865,183.642 h1.52
  text "Bottom Layer" at 259.277,183.642 h1.52
  text "Copper" at 282.892,183.642 h1.52
  text "1.40mil" at 304.731,183.642 h1.52
  text "6" at 248.865,180.594 h1.52
  text "Bottom Solder" at 259.277,180.594 h1.52
  text "Solder Resist" at 282.892,180.594 h1.52
  text "0.40mil" at 304.731,180.594 h1.52
  text "3.5" at 321.236,180.594 h1.52
  text "7" at 248.865,177.546 h1.52
  text "Bottom Overlay" at 259.277,177.546 h1.52
  text ".Layer_Name" at 14.656,-21.806 h1.52
M13 Component Bodies Top:
  text ".Layer_Name" at 14.656,-21.806 h1.52
M14 Component Bodies Bottom:
  text ".Layer_Name" at 14.656,-21.806 h1.52
M15 Courtyards Top:
  text ".Layer_Name" at 14.656,-21.806 h1.52
M16 Courtyards Bottom:
  text ".Layer_Name" at 14.656,-21.806 h1.52
Drill Drawing:
  circle w0.254: c136.238,82.964 r0.702
  lines w0.254: 135.537,79.104 136.94,79.104 136.94,80.508 135.537,80.508 135.537,79.104
  lines w0.305: 134.264,78.157 216.344,78.157 ; 134.264,84.472 216.344,84.472 ; 142.846,74.999 142.846,87.63 ; 151.279,74.999 151.279,87.63 ; 167.448,74.999 167.448,87.63 ; 174.03,74.999 174.03,87.63 ; 183.559,74.999 183.559,87.63 ; 201.957,74.999 201.957,87.63 ; 134.264,74.999 216.344,74.999 216.344,87.63 134.264,87.63 134.264,74.999
  text "Symbol" at 136.159,85.42 h1.83
  text "Quantity" at 143.793,85.42 h1.83
  text "Finished Hole Size" at 152.226,85.42 h1.83
  text "Plated" at 168.395,85.42 h1.83
  text "Hole Type" at 174.977,85.42 h1.83
  text "Drill Layer Pair" at 184.506,85.42 h1.83
  text "Hole Tolerance" at 202.904,85.42 h1.83
  text "22" at 143.793,82.262 h1.52
  text "16.00mil (0.406mm)" at 152.226,82.262 h1.52
  text "PTH" at 168.395,82.262 h1.52
  text "Round" at 174.977,82.262 h1.52
  text "Top Layer - Bottom Layer" at 184.506,82.262 h1.52
  text "4" at 143.793,79.104 h1.52
  text "43.31mil (1.100mm)" at 152.226,79.104 h1.52
  text "PTH" at 168.395,79.104 h1.52
  text "Round" at 174.977,79.104 h1.52
  text "Top Layer - Bottom Layer" at 184.506,79.104 h1.52
  text "26 Total" at 143.793,75.946 h1.52
M17 Embedded Cavity:
  text ".Layer_Name" at 14.656,-21.806 h1.52
M18 Embedded Assembly:
  text ".Layer_Name" at 14.656,-21.806 h1.52
M19 Embedded Keepout:
  text ".Layer_Name" at 14.656,-21.806 h1.52

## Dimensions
-0.762,0 to 50.8,0 on M2 Board Dimensions
-0.762,18.034 to -0.762,0 on M2 Board Dimensions
0,-10.16 to 25.4,-10.16 on M2 Board Dimensions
